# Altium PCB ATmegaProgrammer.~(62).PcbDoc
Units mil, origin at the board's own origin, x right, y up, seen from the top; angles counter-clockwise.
Board outline 2130 x 2720 mil, 2 copper layers (Top Layer, Bottom Layer); 9 components, 8 nets, 64 pads, 4 vias.
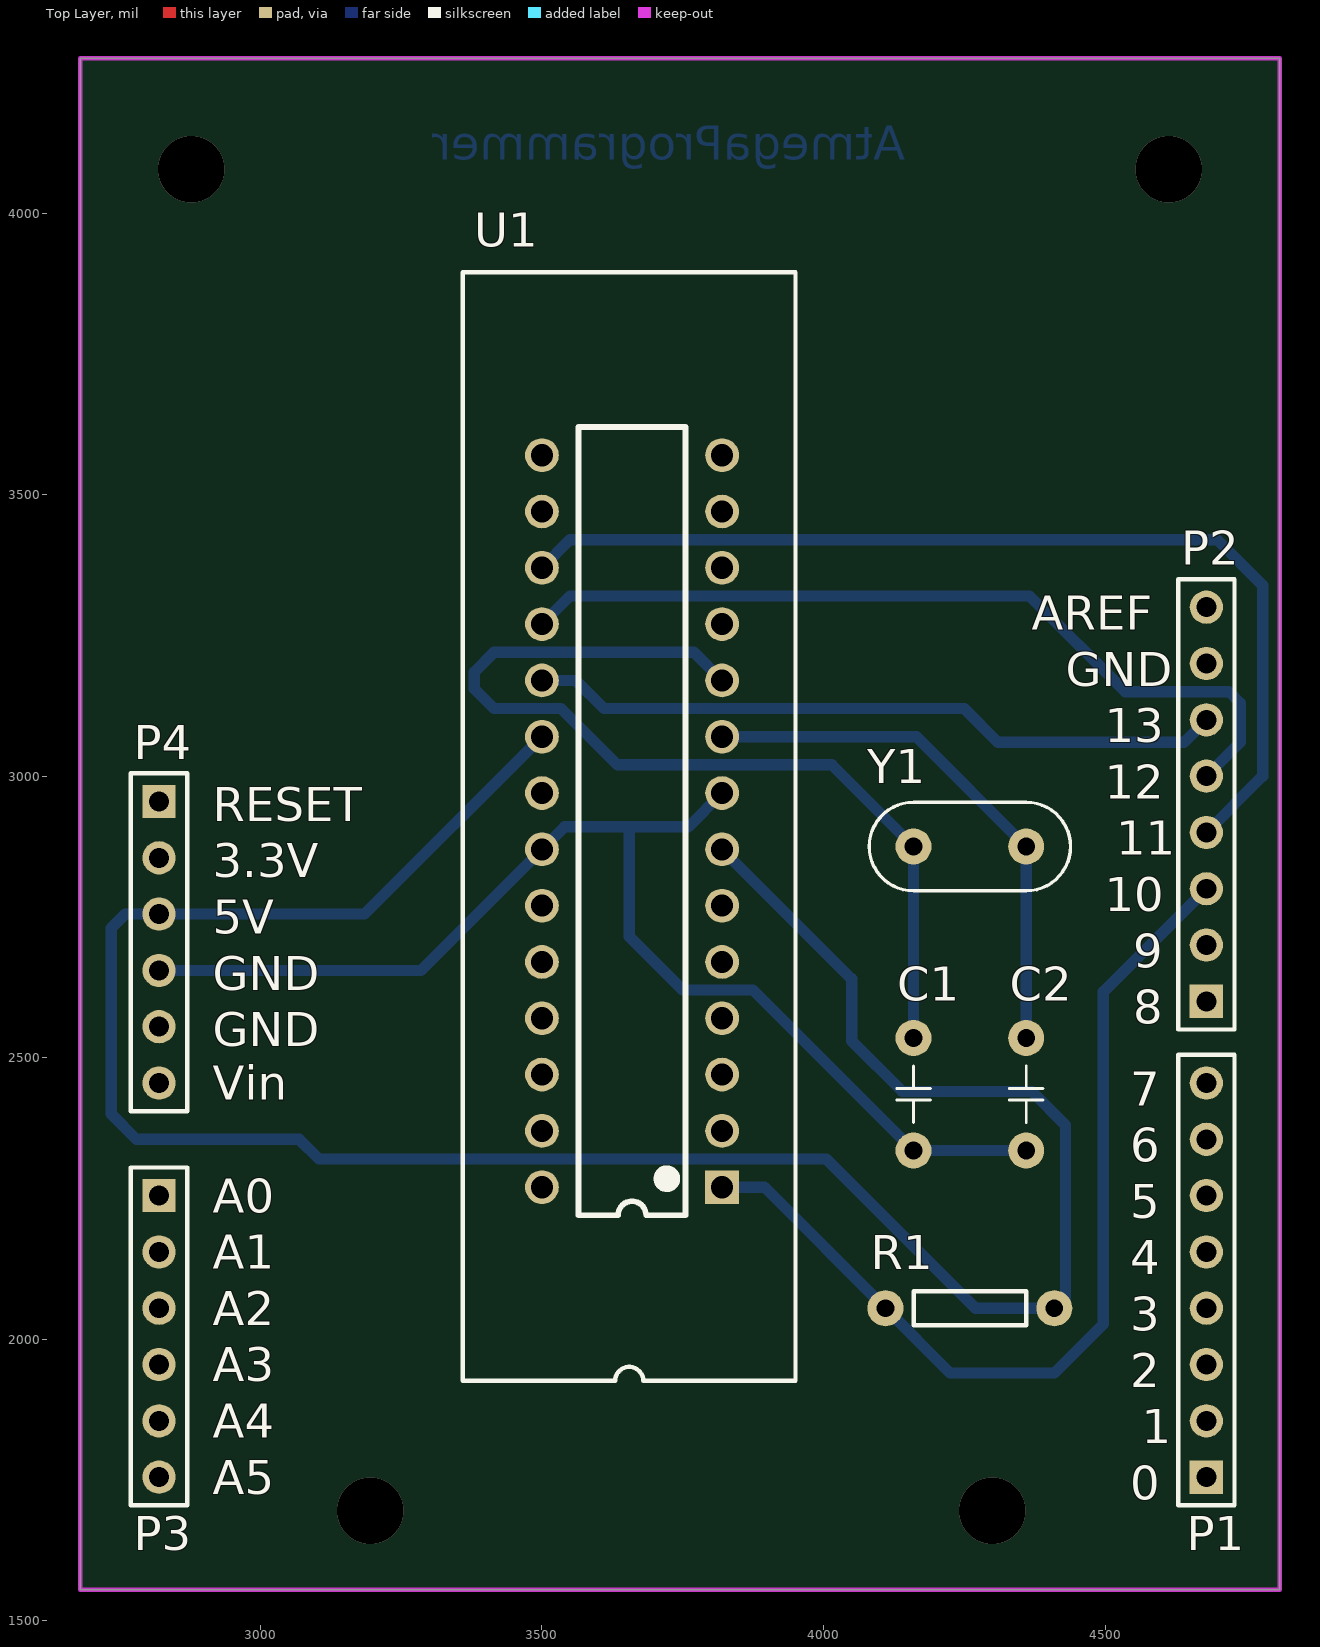
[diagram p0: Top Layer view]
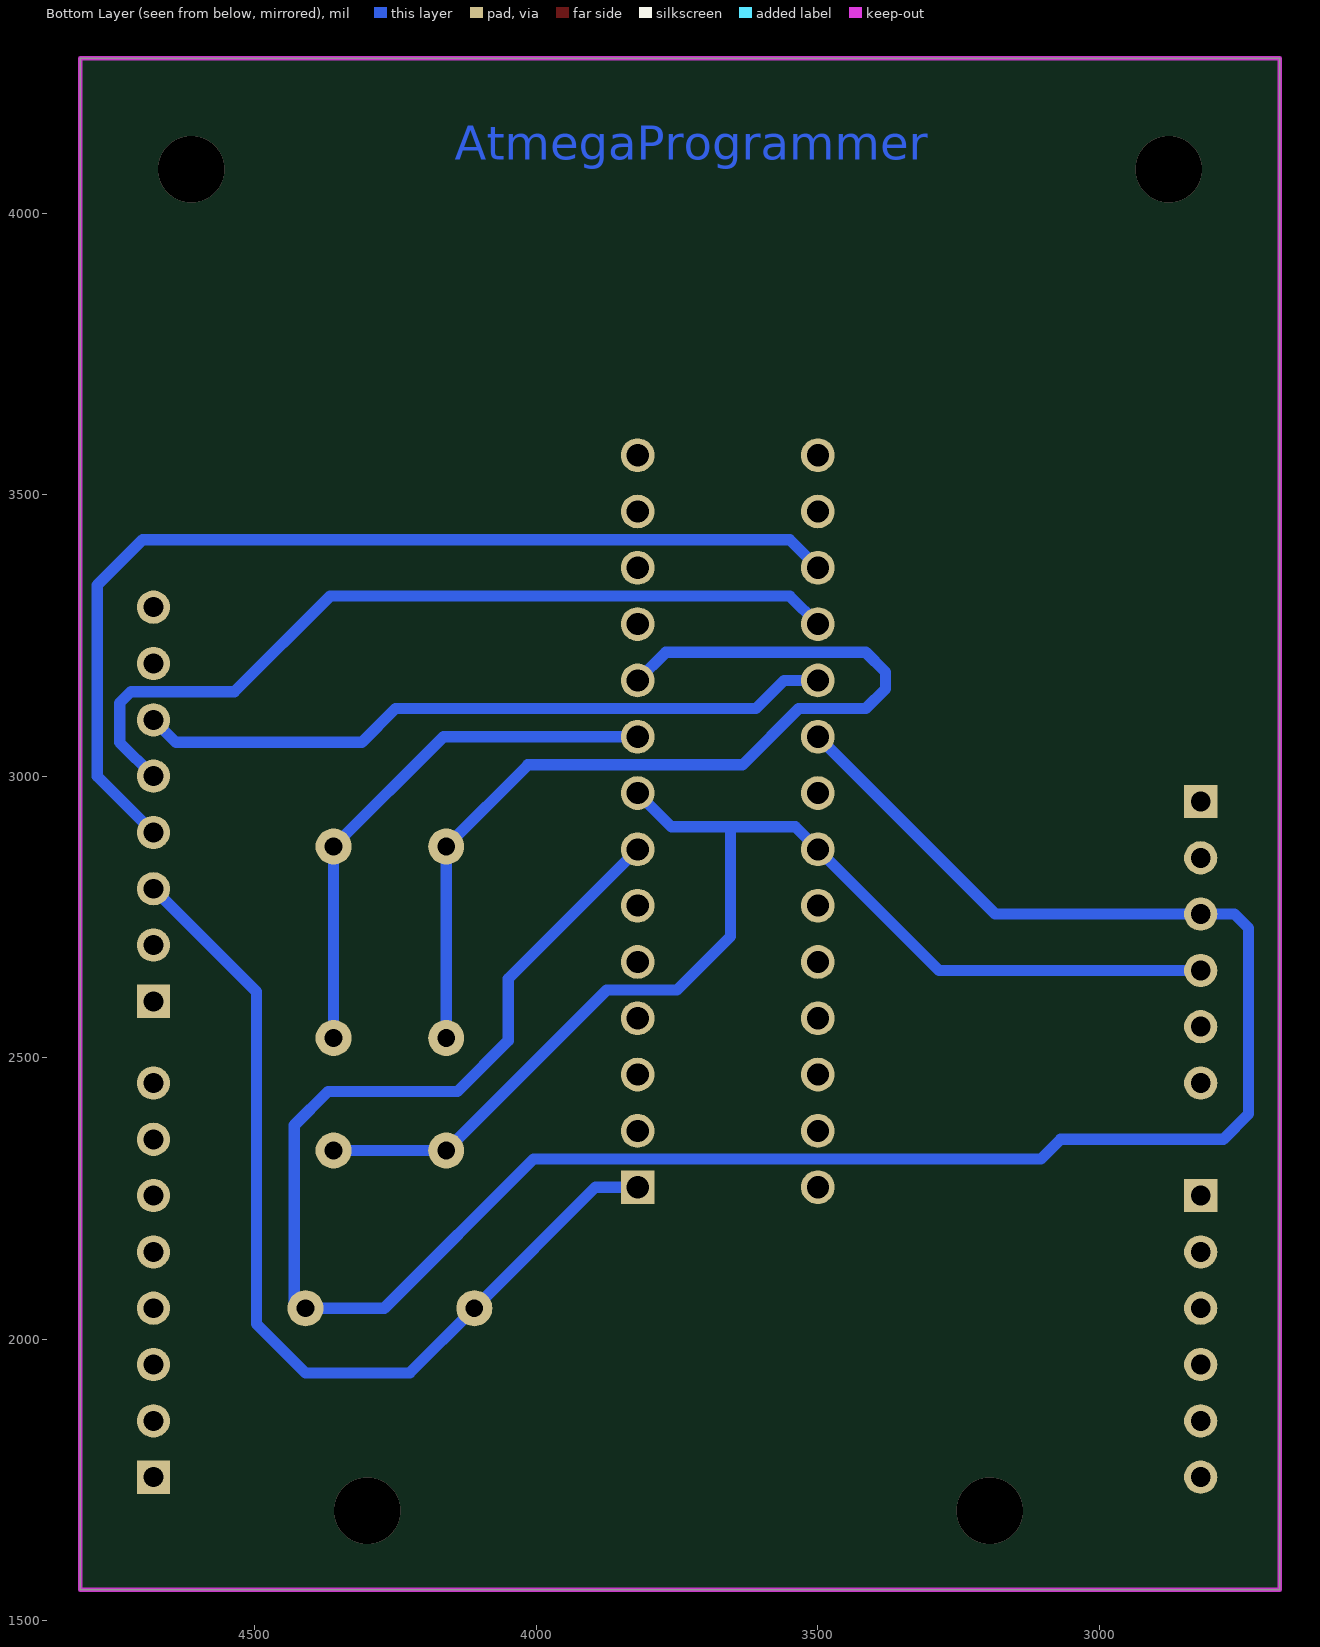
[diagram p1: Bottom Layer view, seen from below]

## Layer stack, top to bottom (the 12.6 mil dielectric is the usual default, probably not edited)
Top Layer: signal copper 1.4
Dielectric: dielectric 12.6, FR-4, Dk 4.8
Bottom Layer: signal copper 1.4

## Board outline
2680,1555 4810,1555 4810,4275 2680,4275

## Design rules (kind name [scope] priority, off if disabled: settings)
Clearance [All] p1: gap=10
PolygonConnect [All] p1: connectstyle=Relief reliefconductorwidth=10 reliefentries=4 polygonreliefangle="90 Angle"
RoutingLayers [All] p1: top layer_v5=FALSE bottom layer_v5=TRUE
RoutingVias [All] p1: holewidth=28 width=50 viastyle="Through Hole" minholewidth=28 minwidth=50 maxholewidth=28 maxwidth=50
SilkscreenOverComponentPads [All] p1: minsilkscreentomaskgap=10
SolderMaskExpansion [All] p1: expansion=4
Width [All] p1: maxlimit=40 minlimit=10 preferedwidth=20
26 further rules are at their usual default settings.

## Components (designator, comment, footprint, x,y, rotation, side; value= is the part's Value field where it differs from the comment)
C1 "20pF" C200 4160,2435 r180 top
C2 "20pF" C200 4360,2435 r180 top
P1 "Header 8" HDR1X8 4680,1755 r90 top
P2 "Header 8" HDR1X8 4680,2600 r90 top
P3 "Header 6" HDR1X6 2820,2255 r270 top
P4 "Header 6" HDR1X6 2820,2955 r270 top
R1 "10k" AXIAL-0.3 4260,2055 r0 top
U1 "ATmega328" "DIP28  socket" 3660,2840 r180 top
Y1 "16MHz" XTAL4-8 4260,2875 r180 top

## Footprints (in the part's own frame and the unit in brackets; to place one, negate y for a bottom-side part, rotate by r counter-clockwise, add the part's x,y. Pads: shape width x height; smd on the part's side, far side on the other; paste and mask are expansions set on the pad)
AXIAL-0.3 [mil] "0.3\" Resistor; 2 Leads"
  round 64 hole 31.5: 1(-150,0) 2(150,0)
  silkscreen extent -100,-30 100,30, body extent -161,-39 165,39, height 86
C200 [mil] "鹅溅筿甧竟"
  round 64 hole 31.5: 1(0,100) 2(0,-100)
  silkscreen extent -30,-50 30,50, body extent -41,-136 39,135, height 354
"DIP28  socket" [mil] "DIP, 28-Pin,Pitch 2.54 mm"
  rect 60x60 hole 39.37: 1(-160,570)
  round 60 hole 39.37: 2(-160,470) 3(-160,370) 4(-160,270) 5(-160,170) 6(-160,70) 7(-160,-30) 8(-160,-130) 9(-160,-230) 10(-160,-330) 11(-160,-430) 12(-160,-530) 13(-160,-630) 14(-160,-730) 15(160,-730) 16(160,-630) 17(160,-530) 18(160,-430) 19(160,-330) 20(160,-230) 21(160,-130) 22(160,-30) 23(160,70) 24(160,170) 25(160,270) 26(160,370) 27(160,470) 28(160,570)
  silkscreen extent -290,-1055 300,914, body extent -290,-1055 300,914, height 130
HDR1X6 [mm] "Connector; Header; 6 Position"
  rect 1.5x1.5 hole 0.9: 1(0,0)
  round 1.5 hole 0.9: 2(2.54,0) 3(5.08,0) 4(7.62,0) 5(10.16,0) 6(12.7,0)
  silkscreen extent -1.27,-1.27 13.97,1.27
HDR1X8 [mm] "Connector; Header; 8 Position"
  rect 1.5x1.5 hole 0.9: 1(0,0)
  round 1.5 hole 0.9: 2(2.54,0) 3(5.08,0) 4(7.62,0) 5(10.16,0) 6(12.7,0) 7(15.24,0) 8(17.78,0)
  silkscreen extent -1.27,-1.27 19.05,1.27
XTAL4-8 [mil]
  round 64 hole 31.5: 1(-100,0) 2(100,0)
  silkscreen extent -179,-79 179,79, body extent -178,-80 192,79, height 157

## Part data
C1 C2: library part Cap, "Capacitor"
P1 P2: "Header, 8-Pin"
P3 P4: "Header, 6-Pin"
R1: library part Res, "Resistor"
U1: "ATmega¨t¦C³æ´¹¤ù"
Y1: library part XTAL, "Crystal Oscillator"

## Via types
v1: diameter 118.11, hole 118.11, Top Layer to Bottom Layer, 4 vias

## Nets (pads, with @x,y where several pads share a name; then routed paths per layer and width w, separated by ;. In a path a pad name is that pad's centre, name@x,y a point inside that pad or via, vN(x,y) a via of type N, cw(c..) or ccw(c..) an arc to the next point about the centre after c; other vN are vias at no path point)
GND: C1.1 C2.1 P4.4 U1.8 U1.22 | length 2187.9
  Bottom Layer w20: P4.4 3285,2655 U1.22 3540,2910 3655,2910 ; U1.8 3760,2910 3655,2910 ; C2.1 C1.1 3875,2620 3750,2620 3655,2715 3655,2910
MISO: P2.5 U1.18 | length 1494.3
  Bottom Layer w20: U1.18 3550,3320 4366,3320 4536,3150 4720,3150 4740,3130 4740,3060 P2.5
MOSI: P2.4 U1.17 | length 1814.7
  Bottom Layer w20: U1.17 3550,3420 4699,3420 4780,3339 4780,3000 P2.4
NetC1_2: C1.2 U1.10 Y1.2 | length 1741.2
  Bottom Layer w20: U1.10 3770,3220 3415,3220 3380,3185 3380,3155 3415,3120 3534,3120 3634,3020 4015,3020 Y1.2 C1.2
NetC2_2: C2.2 U1.9 Y1.1 | length 960.8
  Bottom Layer w20: U1.9 4165,3070 Y1.1 C2.2
RESET: P2.3 R1.1 U1.1 | length 1698.5
  Bottom Layer w20: U1.1 3895,2270 R1.1 4225,1940 4410,1940 4497,2027 4497,2617 P2.3
SCK: P2.6 U1.19 | length 1242.1
  Bottom Layer w20: U1.19 3560,3170 3610,3120 4250,3120 4310,3060 4640,3060 P2.6
VCC: P4.3 R1.2 U1.7 U1.20 | length 4276.1
  Bottom Layer w20: U1.20 3185,2755 2760,2755 2735,2730 2735,2400 2780,2355 3069,2355 3104,2320 4005,2320 4270,2055 4430,2055 4430,2380 4370,2440 4140,2440 4050,2530 4050,2640 U1.7
pads on no net: P1.1 P1.2 P1.3 P1.4 P1.5 P1.6 P1.7 P1.8 P2.1 P2.2 P2.7 P2.8 P3.1 P3.2 P3.3 P3.4 P3.5 P3.6 P4.1 P4.2 P4.5 P4.6 U1.2 U1.3 U1.4 U1.5 U1.6 U1.11 U1.12 U1.13 U1.14 U1.15 U1.16 U1.21 U1.23 U1.24 U1.25 U1.26 U1.27 U1.28
copper on no net:
  other v1: 3195,1695 4300,1695 2876.85,4078.15 4613.15,4078.15

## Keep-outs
Keep-Out Layer:
  the board outline again, w7.87

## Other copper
Bottom Layer:
  text "AtmegaProgrammer" at 4145,4095 h60

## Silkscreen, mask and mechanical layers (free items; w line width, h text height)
Top Overlay:
  lines w7.87: 0,0 0,200 ; 20,0 35,0 ; 55,0 195,0 ; 2770,2246.75 2770,2255
  text "AREF" at 4370,3260 h60
  text "GND" at 4429.98,3160 h60
  text "13" at 4499.96,3060 h60
  text "12" at 4499.96,2960 h60
  text "RESET" at 2915.05,2920 h60
  text "11" at 4519.95,2860 h60
  text "3.3V" at 2915.05,2820 h60
  text "10" at 4499.96,2760 h60
  text "5V" at 2915.05,2720 h60
  text "9" at 4549.94,2660 h60
  text "GND" at 2915.05,2620 h60
  text "8" at 4549.94,2560 h60
  text "GND" at 2915.05,2520 h60
  text "Vin" at 2915.05,2425 h60
  text "7" at 4544.94,2415 h60
  text "6" at 4544.94,2315 h60
  text "A0" at 2915.05,2225 h60
  text "5" at 4544.94,2215 h60
  text "A1" at 2915.05,2125 h60
  text "4" at 4544.94,2115 h60
  text "A2" at 2915.05,2025 h60
  text "3" at 4544.94,2015 h60
  text "A3" at 2915.05,1925 h60
  text "2" at 4544.94,1915 h60
  text "A4" at 2915.05,1825 h60
  text "1" at 4564.94,1815 h60
  text "A5" at 2915.05,1725 h60
  text "0" at 4544.94,1715 h60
